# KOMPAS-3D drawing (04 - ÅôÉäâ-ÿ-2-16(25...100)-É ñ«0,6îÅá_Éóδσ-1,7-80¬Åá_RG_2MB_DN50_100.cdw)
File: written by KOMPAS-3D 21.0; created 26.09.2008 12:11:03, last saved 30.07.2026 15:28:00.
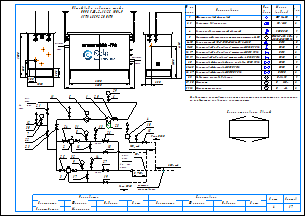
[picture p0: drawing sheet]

Sheets 1-2: A3, landscape

Document properties: Наименование: Макро:21; Автор: RaskoAdmin; Форматы листов документа: 2xA3; Полное имя файла: \\ur38nt01\Departments\КТО\КБ ПУРДГ\Заявки\Прайс-лист на типовые шкафы ГРПШ\ПУРДГ_стандарт_30_04_2026\ПУРДГ с RG_2MB\ПУРДГ-Ш-2-16(25...100)-Р до0,6МПа_Рвых-1,7-80кПа_RG_2MB_DN50_100.cdw

Title block, sheet 1: Наименование: Пункт учета газа / ПУГ-Ш-400-Р / ЛГТИ.485922.001ТУ; designation: ЛГТИ.03.4411141; sheet number: 1; Количество листов документа: 2; organisation: ООО "ЭЛЬСТЕР Газэлектроника"; Форматы листов документа: A3; stored path: C:\Рабочие документы\Компас\ПУГ\Схема.cdw; Разработал: Устинов; Проверил: Кошкин; Утвердил: Кошкин
Title block, sheet 2: sheet number: 2; stored path: D:\Рабочие документы\Заявки\ПУРДГ\ПУРДГ-ШУЭО-2-100-Р 4411220.cdw; designation, second copy: ЛГТИ.03.4411141-

Views: Вид 1, Вид 2
Referenced files: wcvoit.frw
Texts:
  Normal
  № на
  схеме
  Усл.
  обозн.
  Марка
  (модель)
  Кол.
  Фильтр газовый фланцевый
  ФГ 16-50
  Регулятор давления газа
  RG/2MB
  Клапан предохранительный сбросной
  КПС DN20
  Измерительный комплекс с ротационным счетчиком Ду50
  СГ-ЭК-Р-(0,2...2,0)-
  Кран кнопочный VE-РАСКО-НЗ-1,6-G1/2-М20
  DN15
  Кран шаровой "под приварку" штуцерный DN20 PN16
  DN20
  Кран шаровой "под приварку" штуцерный DN15 PN16
  Кран шаровой "под приварку" штуцерный п/п DN20 PN16
  Кран шаровой фланцевый с мех. приводом DN50 PN16
  Кран шаровой фланцевый DN50 PN16
  Кран шаровой фланцевый DN100 PN16
  DN50
  DN100
  Индикатор перепада давления
  Манометр
  Манометр-напоромер
  Delta 15
  0...     МПа
  0...     кПа
  Общий вид и габариты шкафа
  ПУРДГ-Ш-2-16(25...100)-Р
  Выход газа
  Вход газа
  logo-rasko-ge.png
  DN 1
  местное
  сопротивление
  Римп DN20
  Выход
  газа
  Р=     кПа
  Вход
  Р=       МПа
  PDI
  Схема открывания дверей
  Предприятие изготовитель может заменять комплектующие на аналогичные,
  не ухудшающие заявленных характеристик.
  Должность
  Конструктор
  Фамилия
  Подпись
  Дата
  Согласовано
  Максимкин
  Лист
  Листов
  POLYLINE_STYLE_0.18_RGB_0_0_0
  POLYLINE_STYLE_0.50_RGB_0_0_0
  POLYLINE_STYLE_0.34_RGB_0_0_0
  PHANTOM_RGB_0_0_0_SC_1_THICK_0.18
  K5LT_THIN_RGB_0_0_0_THICK_0.18
  K5LT32769_RGB_0_0_0_THICK_0.18
  K5LT12_RGB_0_0_0_SC_1_THICK_0.18
  K5LT_DASHED_RGB_0_0_0_SC_1_THICK_0.18
  ACISOTGL_RGB_0_0_0_SC_0.8_THICK_0.25
  CONTINUOUS_RGB_0_127_31_THICK_0.3
  CONTINUOUS_RGB_0_0_255_THICK_0.35
  CONTINUOUS_RGB_255_0_0_THICK_0.35
  POLYLINE_STYLE_0.25_RGB_0_0_0
  CONTINUOUS_RGB_0_0_0_THICK_0.5
  POLYLINE_STYLE_0.35_RGB_0_0_255
  CONTINUOUS_RGB_0_0_0_THICK_0.4
  CONTINUOUS_RGB_0_0_0_THICK_0.35
  НЕВИДИМАЯ_RGB_0_0_0_SC_0.3_THICK_0.25
  СONTINUOUS_RGB_0_0_0_THICK_0.25
  ОСЕВАЯ2_RGB_248_153_30_SC_0.3_THICK_0.25
  Без оформления
Dimensions and other numbers on the sheet: 1; 2, 3; 2; 4; 5; 6-10; 11-15; 16, 17; 18, 19; 20; 21-25; 26, 27; 28; 29, 30; 31, 32; 1500; 250; 300; 1050; 550; 305; 2300; 4130; 2000; 2600; 5,,,7DN 1; 7; 30; 12; 21; 22; 23; 11; 6; 29; 24; 31; 8; 16; 13; 26; 18; 10; 15; 25; 32; 9; 3; 17; 14; 27; 19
